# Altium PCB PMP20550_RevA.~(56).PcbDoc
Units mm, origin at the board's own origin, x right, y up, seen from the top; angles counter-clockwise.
Board outline 49.95 x 50.01 mm, 4 copper layers (Top Layer, POWER, GNDS, Bottom Layer), stack 2.028 mm thick; 56 components, 23 nets, 129 pads, 61 vias.
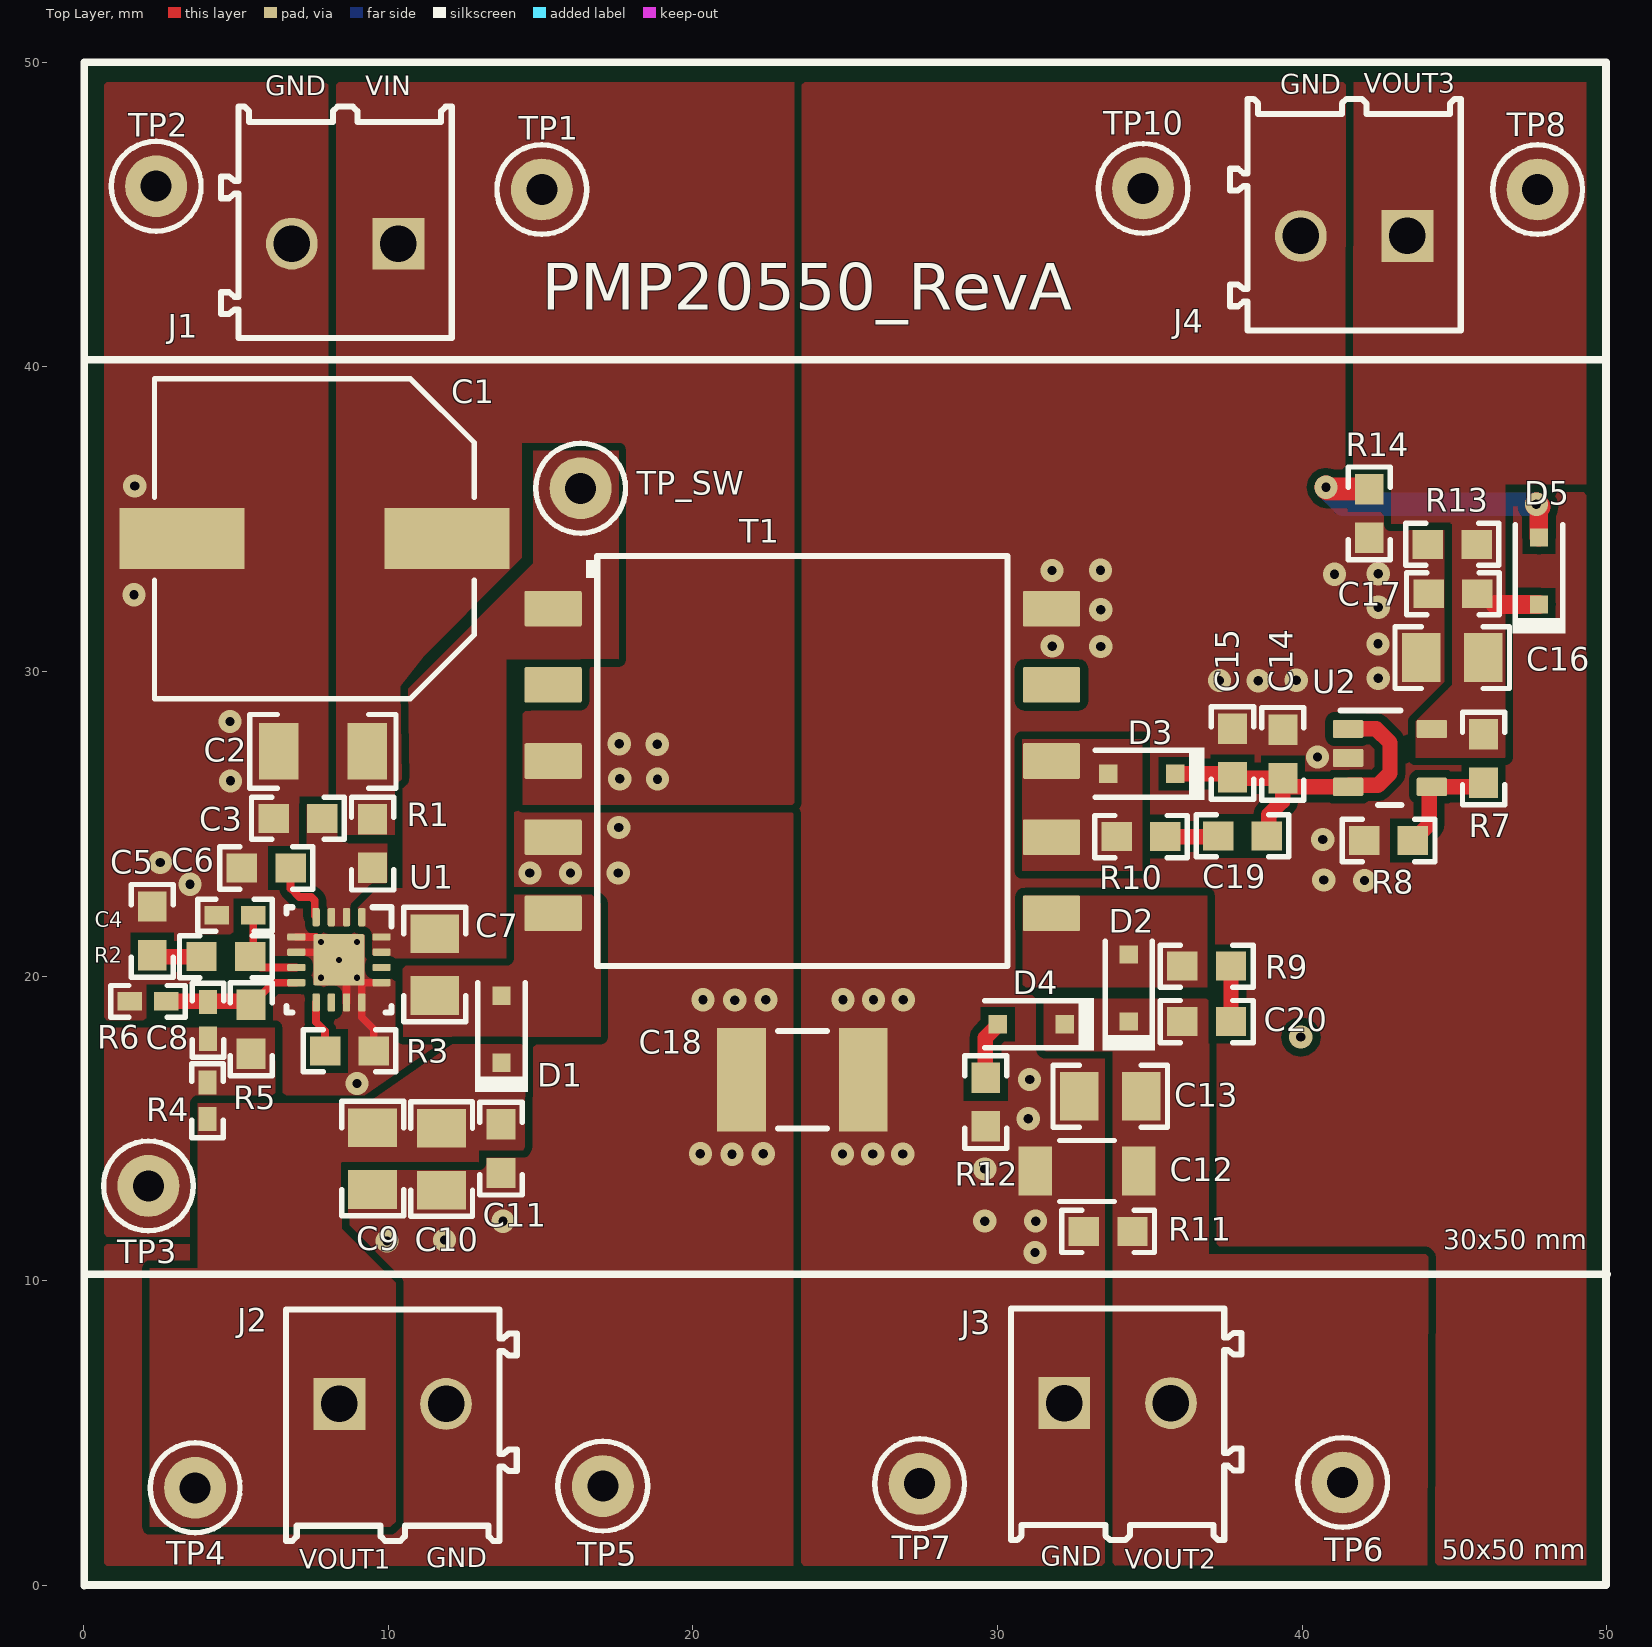
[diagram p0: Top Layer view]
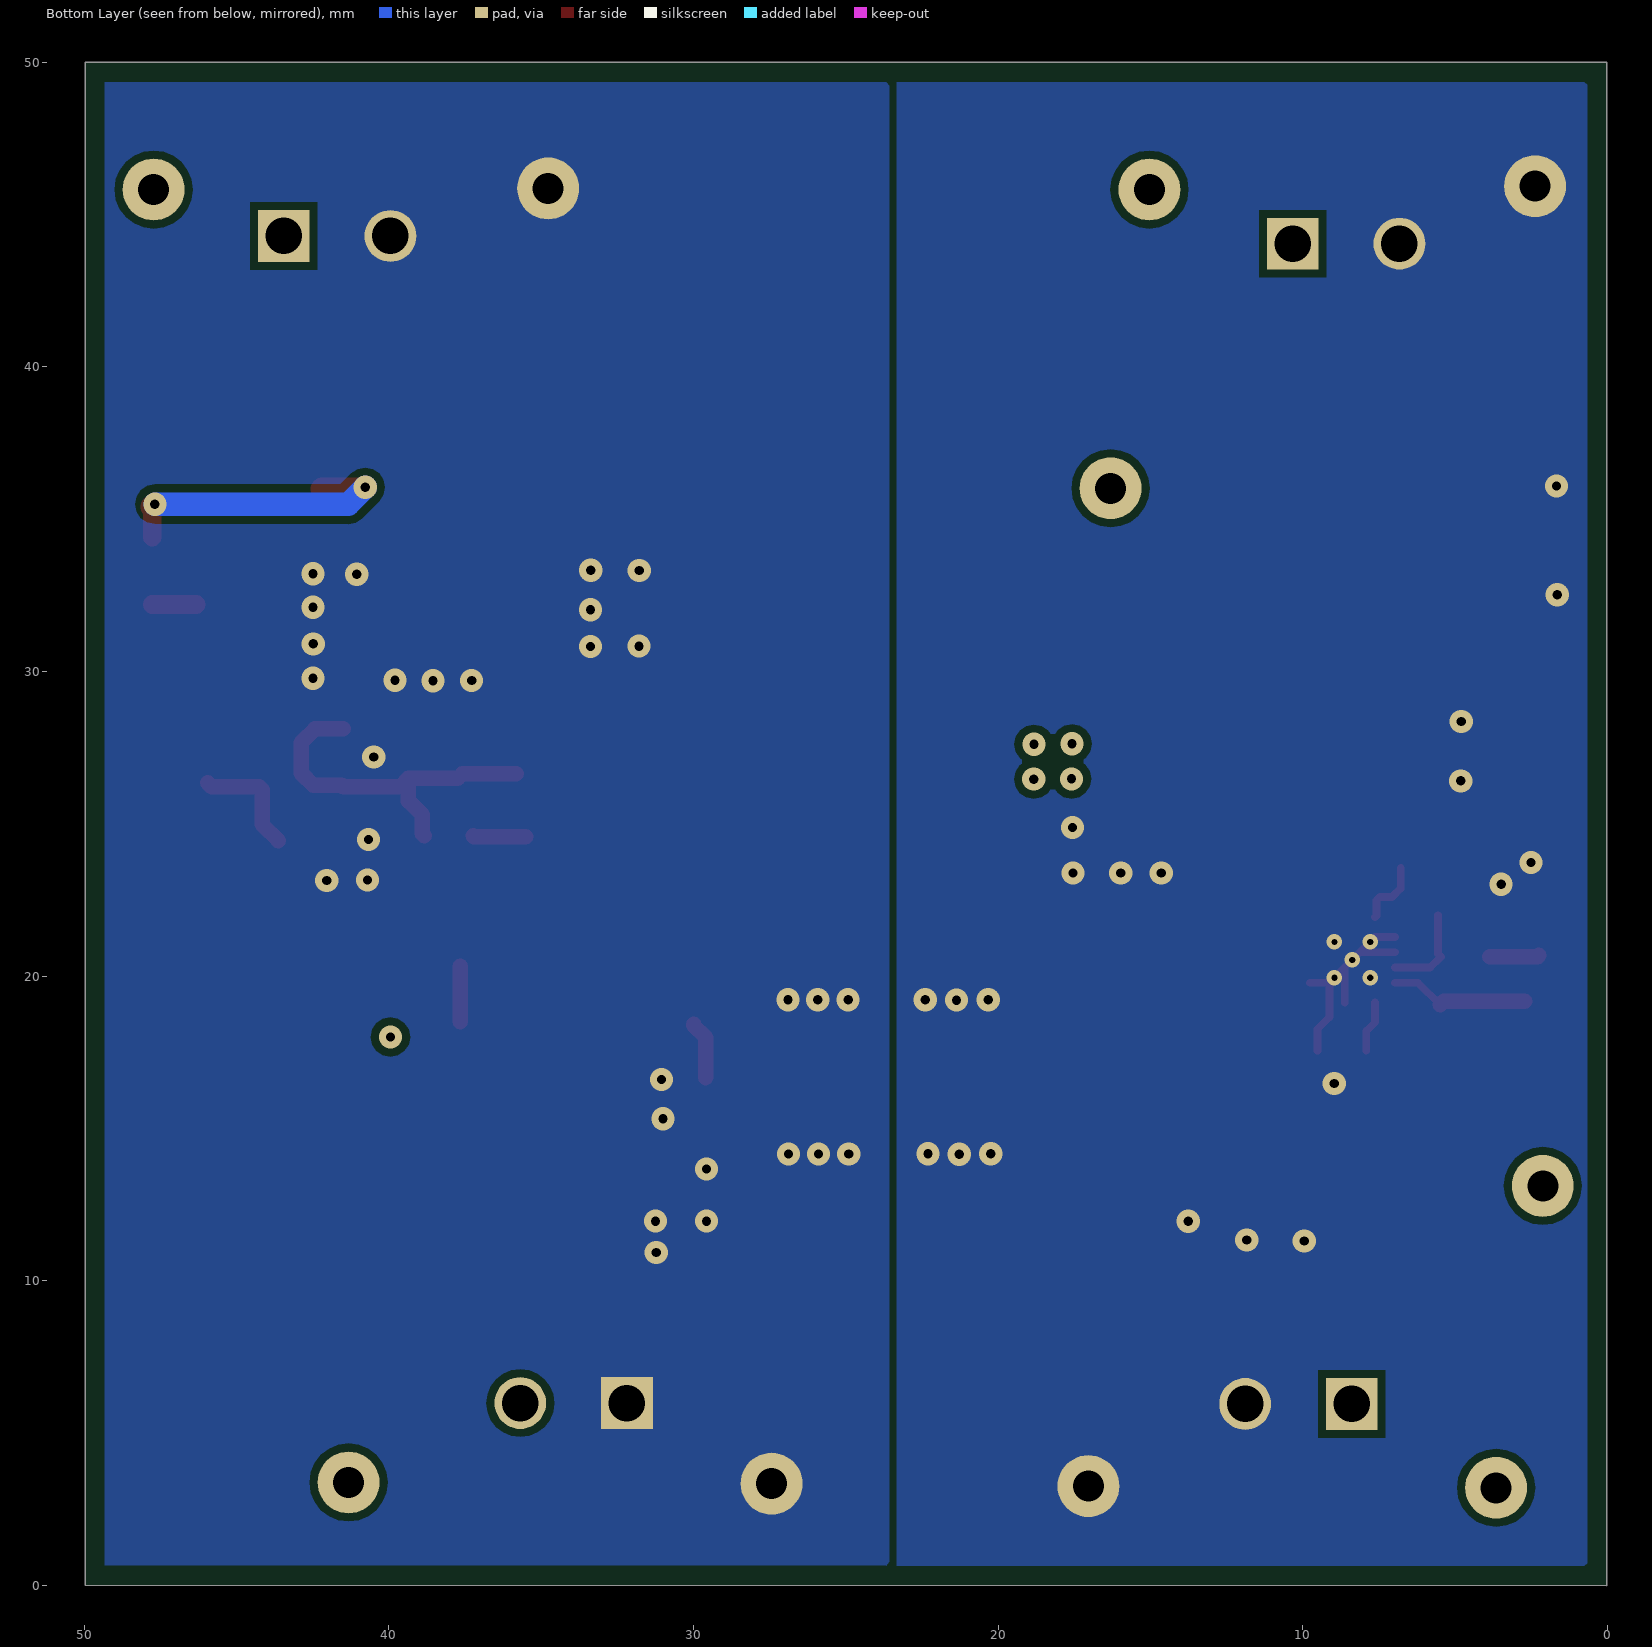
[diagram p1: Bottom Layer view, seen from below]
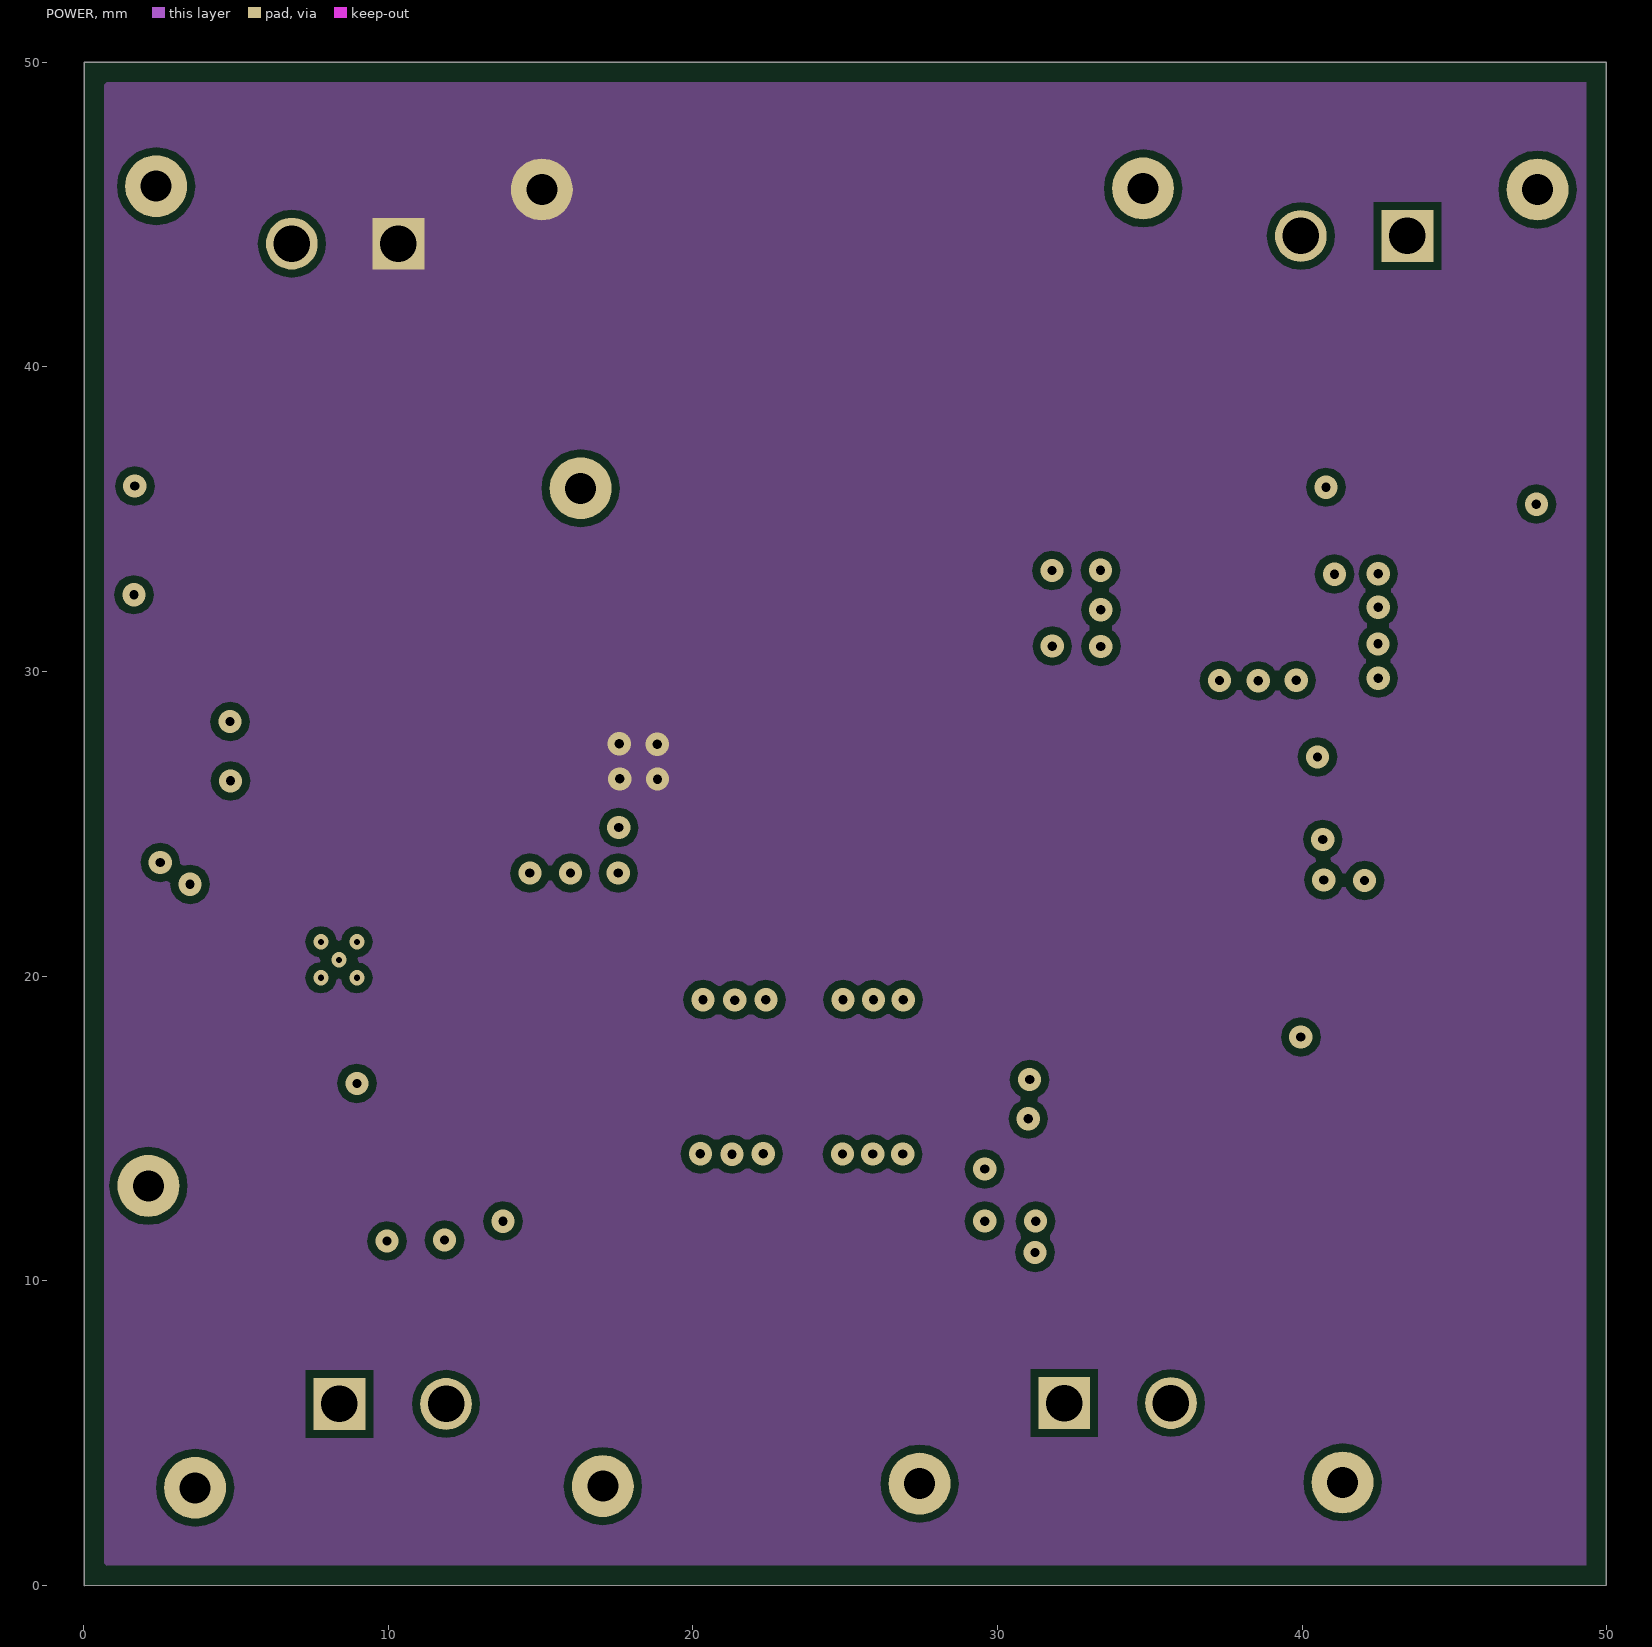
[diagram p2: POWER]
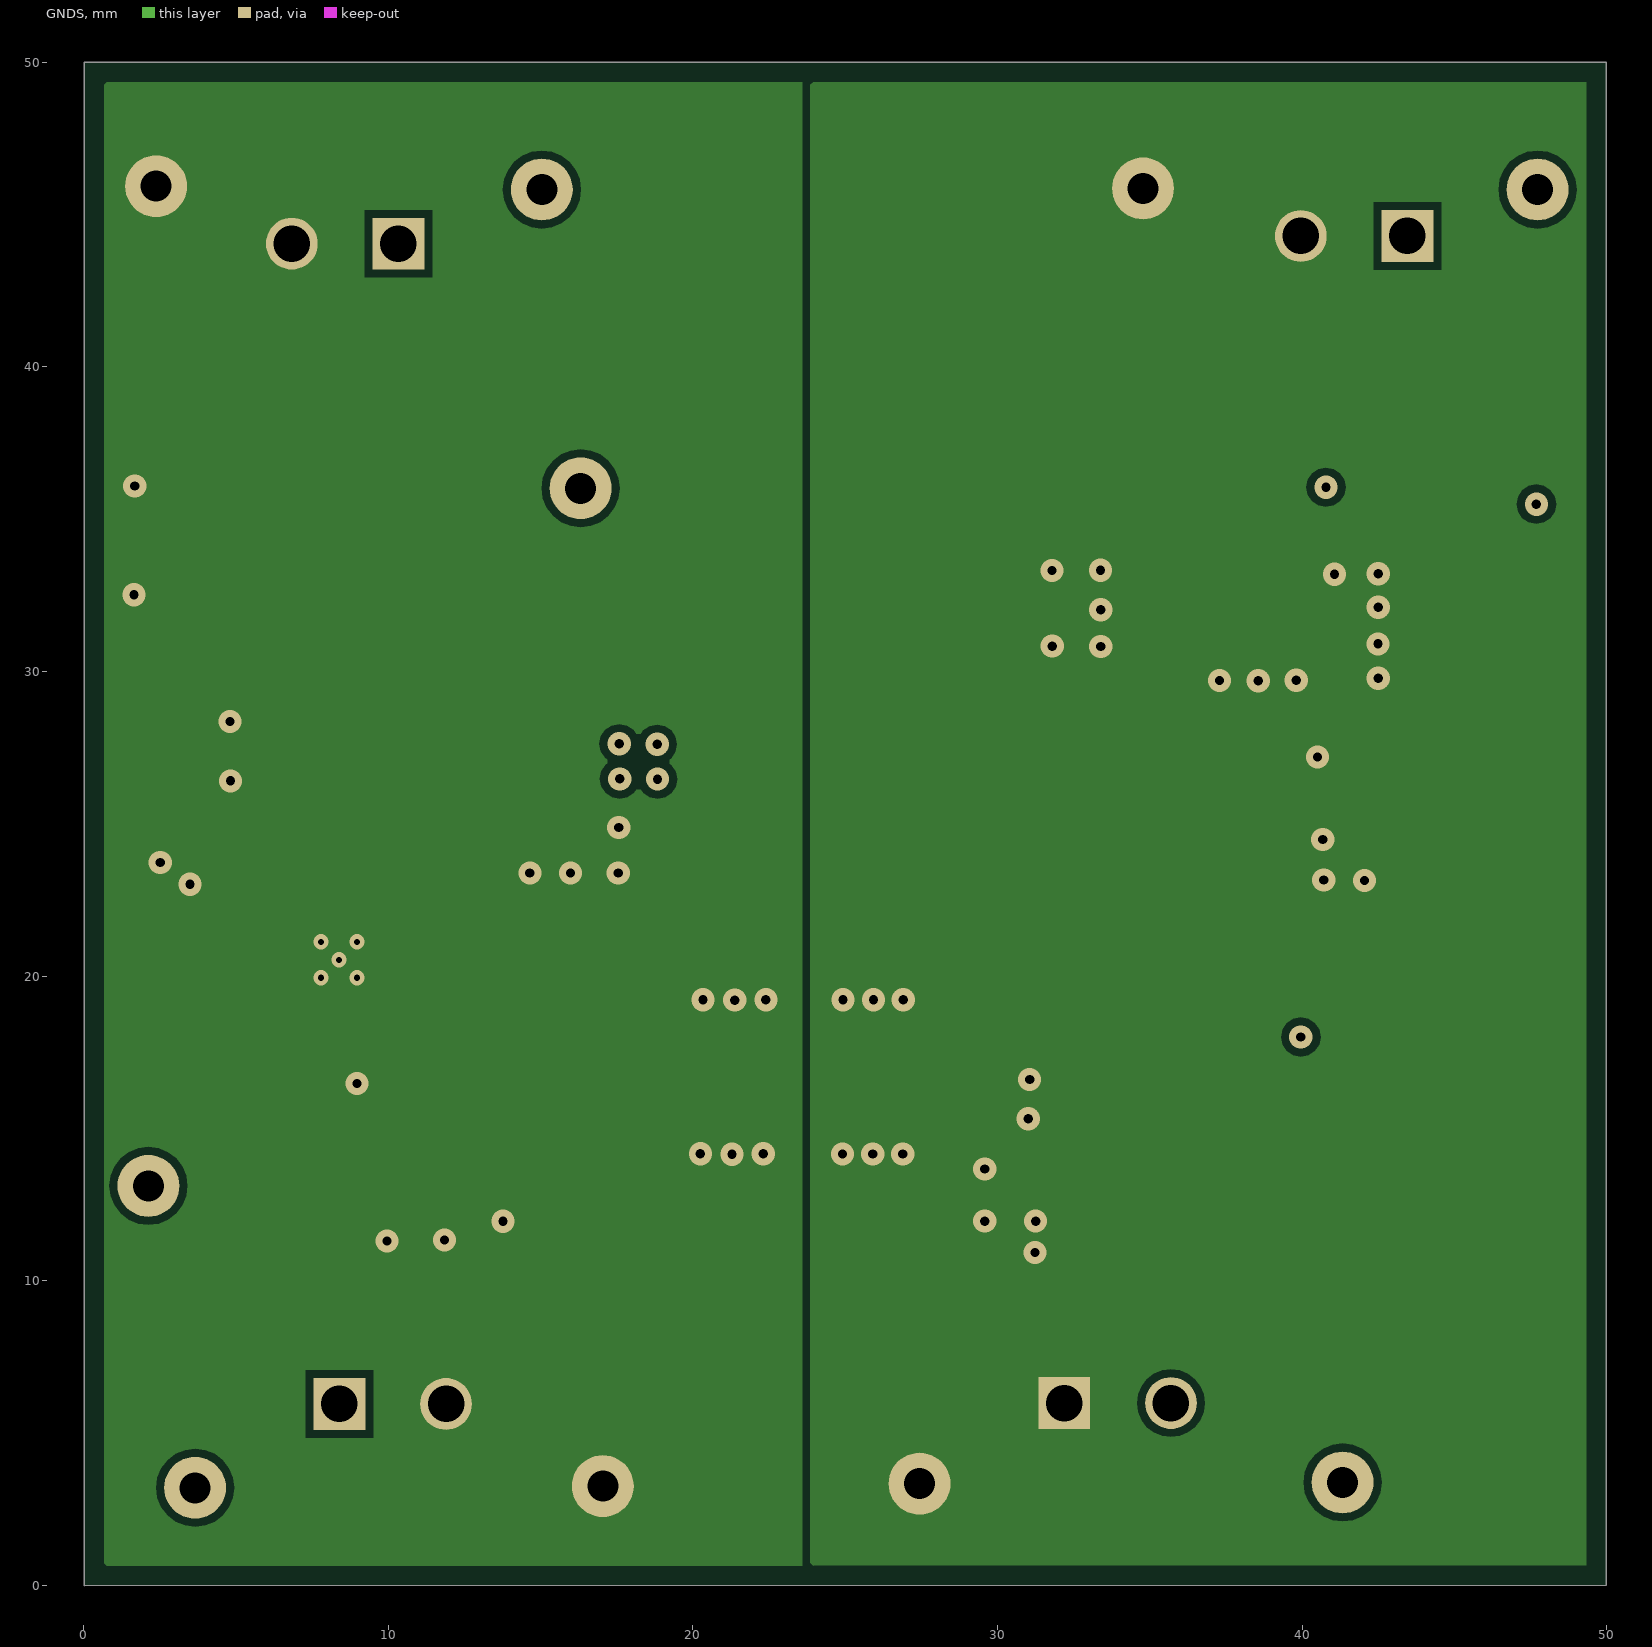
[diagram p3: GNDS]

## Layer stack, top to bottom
Top Solder: solder mask 0.0102, Solder Resist, Dk 3.5
Top Layer: signal copper 0.0356
Dielectric1: core 1.5037, FR-4, Dk 4.8
POWER: signal copper 0.036
Dielectric 3: prepreg 0.127, Dk 4.2
GNDS: signal copper 0.036
Dielectric 2: core 0.254, Dk 4.2
Bottom Layer: signal copper 0.0356
Bottom Solder: solder mask 0.0102, Solder Resist, Dk 3.5

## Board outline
0.019,-0.011 0.019,49.996 0.021,49.994 49.97,49.994 49.972,49.992 49.972,0.008 49.971,0.01

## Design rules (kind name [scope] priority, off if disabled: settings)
AcuteAngle [All] p1: minimum=4.50000000000000E+0001 checktracksonly=FALSE
AssemblyTestPointUsage [All] p1: valid=2
BoardOutlineClearance BoardOutlineClearance_MountingHoles [OnCopper and InComponentClass('Mounting Holes')] p1: gap=1.016
BoardOutlineClearance BoardOutlineClearance_Poly [OnCopper and IsPoly] p2: gap=0.635
BoardOutlineClearance [OnCopper and Not InComponentClass('Logo') and not InComponentClass('FiducialMark') and not InRegion(1000,500,4000,800) and not InPoly] p3: gap=1.016
Clearance Clearance_Keepouts [((IsTrack Or IsArc) And Not InPoly) And IsFree and IsKeepOut vs ((IsTrack Or IsArc) And Not InPoly) And IsFree and IsKeepOut] p1: gap=0
Clearance Clearance_Poly [InPolygon] p2: gap=0.254
Clearance [All] p3: gap=0.127
ComponentClearance ComponentClearance_MountingHoles_FiducialMarks [InComponentClass('Mounting Holes') vs InComponentClass('FiducialMark')] p1: gap=1.27 collisioncheckmode=3 verticalgap=0.254 showdistances=FALSE
ComponentClearance ComponentClearance_Shunt [InComponentClass('Header') vs InComponentClass('Shunt')] p2: gap=0 collisioncheckmode=3 verticalgap=0 showdistances=FALSE
ComponentClearance ComponentClearance_Logo [InComponentClass('Logo')] p3: gap=1.27 collisioncheckmode=3 verticalgap=0.254 showdistances=FALSE
ComponentClearance ComponentClearance_ScrewToNut [(HasFootprint('NY PMS 440 0025 PH')) vs (HasFootprint('Keystone_1902C'))] p4: gap=0.127 collisioncheckmode=3 verticalgap=0.254 showdistances=FALSE
ComponentClearance ComponentClearance_MountingHoles [InComponentClass('Mounting Holes')] p5: gap=6.35 collisioncheckmode=3 verticalgap=2540 showdistances=FALSE
ComponentClearance ComponentClearance_SmallPassives [HasFootprint('0201*') or HasFootprint('0402*') or HasFootprint('0508') or HasFootprint('0603*') or HasFootprint('0612') or HasFootprint('0805*') or HasFootprint('0815*') or HasFootprint('0830*') or HasFootprint('1206*') or HasFootprint('1210*') or HasFootprint('1808*') or HasFootprint('1812*') or HasFootprint('1825*') or HasFootprint('2010*') or HasFootprint('2220*') or HasFootprint('2225*') or HasFootprint('2512*') or HasFootprint('2728*') or HasFootprint('3518*') vs HasFootprint('0201*') or HasFootprint('0402*') or HasFootprint('0508') or HasFootprint('0603*') or HasFootprint('0612') or HasFootprint('0805*') or HasFootprint('0815*') or HasFootprint('0830*') or HasFootprint('1206*') or HasFootprint('1210*') or HasFootprint('1808*') or HasFootprint('1812*') or HasFootprint('1825*') or HasFootprint('2010*') or HasFootprint('2220*') or HasFootprint('2225*') or HasFootprint('2512*') or HasFootprint('2728*') or HasFootprint('3518*')] p6: gap=0.38 collisioncheckmode=3 verticalgap=0.254 showdistances=FALSE
ComponentClearance ComponentClearance_THtoSMT [IsThruComponent vs IsSMTComponent] p7: gap=1.016 collisioncheckmode=3 verticalgap=0.762 showdistances=FALSE
ComponentClearance ComponentClearance_THtoTH [IsThruComponent vs IsThruComponent] p8: gap=0.762 collisioncheckmode=3 verticalgap=0.762 showdistances=FALSE
ComponentClearance [All] p9: gap=0.762 collisioncheckmode=3 verticalgap=0.254 showdistances=FALSE
DiffPairsRouting [All] p1: maxlimit=2.54 minlimit=0.254 mostfreqgap=0.254 toplayer_minwidth=0.381 toplayer_maxwidth=0.381 toplayer_prefwidth=0.381 midlayer1_minwidth=0.381 midlayer1_maxwidth=0.381 midlayer1_prefwidth=0.381 midlayer2_minwidth=0.381 midlayer2_maxwidth=0.381 midlayer2_prefwidth=0.381 bottomlayer_minwidth=0.381 bottomlayer_maxwidth=0.381 bottomlayer_prefwidth=0.381 maxuncoupledlength=25.4
FabricationTestPointUsage TestPointUsage [All] p1: valid=2 allowmultiple=FALSE
FabricationTestpoint Testpoint [All] p1: side=3 testpointundercomponent=TRUE minsize=1.016 maxsize=2.54 preferedsize=1.524 minholesize=0 maxholesize=1.016 preferedholesize=0.813 testpointgrid=0.025 allowsidetop=TRUE allowsidebottom=TRUE usegrid=TRUE gridtolerance=0
FanoutControl Fanout_LCC [IsLCC] p1: bgadir=Out bgaviamode=Centered fanoutstyle=Auto fanoutdirection=Alternating viagrid=0.025 // Fanout_LCC (Default Rule)
FanoutControl Fanout_BGA [IsBGA] p2: bgadir=Out bgaviamode=Centered fanoutstyle=Auto fanoutdirection=Alternating viagrid=0.025 // Fanout_BGA (Default Rule)
FanoutControl Fanout_Default [All] p4: bgadir=Out bgaviamode=Centered fanoutstyle=Auto fanoutdirection=Alternating viagrid=0.025 // Fanout_Default (Default Rule)
FanoutControl Fanout_Small [(CompPinCount < 5)] p5: bgadir=Out bgaviamode=Centered fanoutstyle=Auto fanoutdirection=OutThenIn viagrid=0.025 // Fanout_Small (Default Rule)
HoleSize [All] p1: absolutevalues=TRUE maxlimit=6.375 minlimit=0.2 maxpercent=80.000 minpercent=20.000
MinimumAnnularRing MinimumAnnularRing_ThermalPadVias [IsVia and InAnyComponent] p1: minimumring=0.15
MinimumAnnularRing [All] p2: minimumring=0.203
MinimumSolderMaskSliver MinimumSolderMaskSliver_Logo [InComponentClass('Logo') vs InComponentClass('Logo')] p1: minsoldermaskwidth=0.018
MinimumSolderMaskSliver [All] p2: minsoldermaskwidth=0.1
PlaneConnect [All] p1: planeconnectstyle=Direct reliefexpansion=0.254 reliefentries=4 reliefconductorwidth=0.254 reliefairgap=0.254
PolygonConnect [All] p1: connectstyle=Direct reliefconductorwidth=0.254 reliefentries=4 polygonreliefangle="90 Angle" airgapwidth=0.254
RoutingVias ThermalPadVias [IsVia and InAnyComponent] p1: holewidth=0.2 width=0.5 viastyle="Through Hole" minholewidth=0.2 minwidth=0.5 maxholewidth=0.33 maxwidth=0.6
RoutingVias [All] p2: holewidth=0.406 width=0.864 viastyle="Through Hole" minholewidth=0.2 minwidth=0.66 maxholewidth=1.016 maxwidth=1.651
SilkToBoardRegionClearance [Not ((IsComment or IsDesignator) And (Hide <> 'False')) and not InRegion(1000,500,4000,800)] p1:
SilkToSilkClearance SilkToSilkClearance_Pb-FreeLogo [(HasFootprint('Pb-Free_Overlay_Medium') OR HasFootprint('Pb-Free_Overlay_Small')) vs (HasFootprint('Pb-Free_Overlay_Medium') OR HasFootprint('Pb-Free_Overlay_Small'))] p1: silktosilkclearance=0
SilkToSilkClearance [All] p2: silktosilkclearance=0
SilkToSolderMaskClearance SilkToComponentPadClearance [IsPad and InAnycomponent] p1: minsilkscreentomaskgap=0.127 clearancetoexposedcopper=TRUE
SilkToSolderMaskClearance "Silk to Solder Mask Opening" [All] p2: minsilkscreentomaskgap=0.102 clearancetoexposedcopper=FALSE
SolderMaskExpansion [All] p1: expansion=0.05
Width [All] p1: maxlimit=2.54 minlimit=0.152 preferedwidth=0.254 checkconnectedcopper=TRUE
15 further rules are at their usual default settings.

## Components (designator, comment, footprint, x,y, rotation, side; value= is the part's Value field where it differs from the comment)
C1 "EEE-FC1V221P" SM_RADIAL_G 7.574,34.358 r180 top
C2 "GMK316AB7106KL" 1206 7.85,27.378 r180 top
C3 "C1608X7R1E104K080AA" 0603 7.031,25.179 r180 top
C4 "GRM155R71E333KA88D" 0402 4.962,21.998 r180 top
C5 "C1608X7R1E104K080AA" 0603 2.249,21.484 r90 top
C6 "C1608X7R1E104K080AA" 0603 5.991,23.549 r180 top
C7 "LMK212B7105KG-T" 0805_HV 11.52,20.379 r90 top
C8 "GRM1555C1H201JA01D" 0402 4.079,18.549 r90 top
C9 "GRM21BZ71A226ME15L" 0805_HV 9.483,14.008 r270 top
C10 "GRM21BZ71A226ME15L" 0805_HV 11.745,13.991 r270 top
C11 "C0603X104K8RACTU" 0603 13.696,14.336 r270 top
C12 "C3216X5R1E336M160AC" 1206_180 32.928,13.604 r180 top
C13 "08053C104KAT2A" 0805_HV 33.698,16.058 r180 top
C14 "GRM188Z71A106MA73D" 0603 39.362,27.294 r90 top
C15 "C1608X7R1E104K080AA" 0603 37.711,27.322 r90 top
C16 "C2012X7R1E474K125AA" 0805_HV 44.924,30.457 r180 top
C17 "C0603X104K8RACTU" 0603 44.947,32.552 r180 top
C18 "GR443QR73D102KW01L" 1812 23.59,16.598 r180 top
C19 "GRM1885C1H111JA01D" 0603 38.039,24.604 r180 top
C20 "GRM1885C1H111JA01D" 0603 36.861,18.506 r0 top
D1 "PMEG2020EJ,115" SOD-323F 13.713,18.255 r90 top
D2 "PMEG2020EJ,115" SOD-323F 34.302,19.612 r90 top
D3 "PMEG2020EJ,115" SOD-323F 34.728,26.641 r180 top
D4 "MMSZ5235BS-7-F" SOD-323 31.101,18.418 r180 top
D5 "MMSZ5235BS-7-F" SOD-323 47.77,33.299 r90 top
J1 "1984617" Phoenix_1984617 8.58,44.042 r180 top
J2 "1984617" Phoenix_1984617 10.143,5.956 r0 top
J3 "1984617" Phoenix_1984617 33.94,5.983 r0 top
J4 "1984617" Phoenix_1984617 41.703,44.297 r180 top
R1 "ERJ-3GEY0R00V" 0603 9.483,24.35 r90 top
R2 "RC0603FR-073K01L" 0603 4.666,20.638 r0 top
R3 "CRCW0603162KFKEA" 0603 8.723,17.547 r180 top
R4 "ERJ-2RKF49R9X" 0402 4.062,15.907 r270 top
R5 "CRCW060330K9FKEA" 0603 5.495,18.255 r270 top
R6 "ERJ-2RKF1002X" 0402 2.111,19.17 r0 top
R7 "RC0603FR-0778K7L" 0603 45.953,27.143 r90 top
R8 "CRCW060324K9FKEA" 0603 42.833,24.45 r0 top
R9 "CPF0603B1K62E" 0603 36.861,20.324 r180 top
R10 "CPF0603B1K62E" 0603 34.705,24.581 r180 top
R11 "CPF0603B1K62E" 0603 33.627,11.618 r180 top
R12 "CPF0603B1K62E" 0603 29.609,15.864 r270 top
R13 "CPF0603B1K62E" 0603 44.924,34.173 r180 top
R14 "CPF0603B1K62E" 0603 42.198,35.187 r270 top
T1 "750316553" Wurth_750316553 23.588,27.06 r0 top
TP1 "5000" Keystone5000 15.038,45.82 r90 top
TP2 "5001" Keystone5001 2.377,45.929 r90 top
TP3 "5003" Keystone5003 2.124,13.113 r0 top
TP4 "VBUS" Keystone5000 3.656,3.203 r90 top
TP5 "5001" Keystone5001 17.039,3.257 r90 top
TP6 "5000" Keystone5000 41.326,3.378 r0 top
TP7 "5001" Keystone5001 27.438,3.338 r0 top
TP8 "5000" Keystone5000 47.725,45.82 r0 top
TP10 "5001" Keystone5001 34.774,45.857 r90 top
TP_SW "5001" Keystone5001 16.312,36.013 r90 top
U1 "TPS55340QRTERQ1" RTE0016C 8.378,20.534 r270 top
U2 "TPS73201QDBVRQ1" DBV0005A_N 42.88,27.162 r0 top

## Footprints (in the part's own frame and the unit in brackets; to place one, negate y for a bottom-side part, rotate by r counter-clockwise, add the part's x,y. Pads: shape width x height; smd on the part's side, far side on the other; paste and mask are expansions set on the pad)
0402 [mm] "0402 from SM-752 data"
  rect 0.8x0.6 smd: 1(-0.6,0) 2(0.6,0)
  silkscreen extent -1.22,-0.52 1.22,0.52, body extent -0.55,-0.3 0.55,0.3, height 0.6
0603 [mm] "0603 from SM-752 data"
  rect 1x0.95 smd: 1(-0.8,0) 2(0.8,0)
  silkscreen extent -1.52,-0.69 1.52,0.69, body extent -0.87,-0.47 0.87,0.47, height 1
0805_HV [mil] "0805 with 30mil clearance between pads"
  rect 50x63 smd: 1(-40,0) 2(40,0)
  silkscreen extent -74,-40 74,40, body extent -43,-29 43,29, height 57
1206 [mm] "1206 from SM-752 data"
  rect 1.3x1.85 smd: 1(-1.45,0) 2(1.45,0)
  silkscreen extent -2.4,-1.21 2.4,1.21, body extent -1.7,-0.9 1.7,0.9, height 1.35
1206_180 [mm] "1206_180"
  rect 1.1x1.6 smd: 1(-1.7,0) 2(1.7,0)
  silkscreen extent -0.9,-1 0.9,1, body extent -1.75,-0.95 1.75,0.95, height 1.8
1812 [mm]
  rect 1.6x3.4 smd: 1(-2,0) 2(2,0)
  silkscreen extent -0.8,-1.6 0.8,1.6, body extent -2.4,-1.7 2.4,1.7, height 1.35
DBV0005A_N [mm] "SOT23, 5-Leads, Body 2.9x1.6mm, Pitch 0.95mm, Lead Span 2.8mm, IPC Medium Density"
  rrect17% 1x0.6 smd: 1(-1.375,0.95) 2(-1.375,0) 3(-1.375,-0.95) 4(1.375,-0.95) 5(1.375,0.95)
  silkscreen extent -1.63,-1.55 0.38,1.55, body extent -1.42,-1.46 1.42,1.46, height 1.09
Keystone5000 [mil] "For Keystone 500x miniature loop terminals"
  round 80 hole 40: 1(0,0)
  silkscreen extent -58,-58 58,58, body extent -49,-49 49,49, height 182
Keystone5001 [mil] "For Keystone 500x miniature loop terminals"
  round 80 hole 40: 1(0,0)
  silkscreen extent -58,-58 58,58, body extent -49,-49 49,49, height 182
Keystone5003 [mil] "For Keystone 500x miniature loop terminals"
  round 80 hole 40: 1(0,0)
  silkscreen extent -58,-58 58,58, body extent -49,-49 49,49, height 182
Phoenix_1984617 [mm] "Terminal Block, 3.5mm, 2x1, TH"
  rect 1.7x1.7 hole 1.2: 1(-1.75,0)
  round 1.7 hole 1.2: 2(1.75,0)
  silkscreen extent -3.5,-4.5 4.07,3.1, body extent -3.5,-4.5 4.07,3.1, height 9
RTE0016C [mm] "Texas Insturments"
  rrect42% 0.6x0.24 smd: 1(-1.4,0.75) 2(-1.4,0.25) 3(-1.4,-0.25) 4(-1.4,-0.75) 9(1.4,-0.75) 10(1.4,-0.25) 11(1.4,0.25) 12(1.4,0.75)
  rrect42% 0.24x0.6 smd: 5(-0.75,-1.4) 6(-0.25,-1.4) 7(0.25,-1.4) 8(0.75,-1.4) 13(0.75,1.4) 14(0.25,1.4) 15(-0.25,1.4) 16(-0.75,1.4)
  rrect6% 1.55x1.55 on Top Paste: 17(0,0)
  rrect6% 1.68x1.68 smd paste-0.85: 17(0,0)
  silkscreen extent -1.72,-1.73 1.72,1.73, body extent -1.57,-1.57 1.58,1.58, height 0.81
SM_RADIAL_G [mm] "10 x 10.2mm:  Panasonic G"
  rect 4.1x2 smd: 1(-4.35,0) 2(4.35,0)
  silkscreen extent -5.25,-5.25 5.25,5.25, body extent -5.25,-5.25 5.25,5.25, height 10.5
SOD-323 [mm] "NXP recommended land pattern"
  rect 0.6x0.6 smd paste-0.05: 1(-1.1,0) 2(1.1,0)
  silkscreen extent -2.06,-0.86 1.53,0.86, body extent -1.3,-0.67 1.3,0.68, height 1.1
SOD-323F [mm] "NXP recommended land pattern"
  rect 0.6x0.6 smd paste-0.05: 1(-1.1,0) 2(1.1,0)
  silkscreen extent -2.06,-0.86 1.53,0.86, body extent -1.35,-0.67 1.35,0.68, height 0.79
Wurth_750316553 [mm] "SMD, 10-Leads, Body 17.75x13.46mm, Pitch 2.5mm"
  rrect9% 1.88x1.17 smd: 1(-8.18,5) 2(-8.18,2.5) 3(-8.18,0) 4(-8.18,-2.5) 5(-8.18,-5) 6(8.18,-5) 7(8.18,-2.5) 8(8.18,0) 9(8.18,2.5) 10(8.18,5)
  silkscreen extent -7.1,-6.73 6.73,6.73, body extent -8.87,-6.73 8.88,6.73, height 12.7

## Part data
C1: "CAP, AL, 220 µF, 35 V, +/- 20%, 0.15 ohm, SMD"
C2: "CAP, CERM, 10 µF, 35 V, +/- 10%, X7R, 1206"
C3 C5 C6 C15: "CAP, CERM, 0.1 µF, 25 V, +/- 10%, X7R, 0603"
C4: "OPEN, 0402"
C7: "CAP, CERM, 1 µF, 10 V, +/- 10%, X7R, 0805"
C8: "CAP, CERM, 200 pF, 50 V, +/- 5%, C0G/NP0, 0402"
C9 C10: "CAP, CERM, 22 µF, 10 V, +/- 20%, X7R, 0805"
C11 C17: "CAP, CERM, 0.1 µF, 10 V, +/- 10%, X7R, 0603"
C12: "CAP, CERM, 33 µF, 25 V, +/- 20%, X5R, 1206"
C13: "CAP, CERM, 0.1 µF, 25 V, +/- 10%, X7R, 0805"
C14: "CAP, CERM, 10 µF, 10 V, +/- 20%, X7R, 0603"
C16: "CAP, CERM, 4.7 µF, 25 V, +/- 10%, X7R, 0805"
C18: "CAP, CERM, 1000 pF, 2000 V, +/- 10%, X7R, 1812"
C19 C20: "CAP, CERM, 110 pF, 50 V, +/- 5%, C0G/NP0, 0603"
D1 D2 D3: "Diode, Schottky, 20 V, 2 A, SOD-323F"
D4 D5: "Diode, Zener, 6.8 V, 200 mW, SOD-323"
J1 J2 J3 J4: "Terminal Block, 3.5mm, 2x1, TH"
R1: "RES, 0, 5%, 0.1 W, 0603"
R2: "RES, 3.01 k, 1%, 0.1 W, 0603"
R3: "RES, 162 k, 1%, 0.1 W, 0603"
R4: "RES, 49.9, 1%, 0.1 W, AEC-Q200 Grade 0, 0402"
R5: "RES, 30.9 k, 1%, 0.1 W, 0603"
R6: "RES, 10.0 k, 1%, 0.1 W, 0402"
R7: "RES, 78.7 k, 1%, 0.1 W, 0603"
R8: "RES, 24.9 k, 1%, 0.1 W, 0603"
R9 R10 R11 R12 R13 R14: "RES, 1.62 k, 0.1%, 0.063 W, 0603"
T1: "Transformer, 52 uH, SMT"
TP1 TP6 TP8: "Test Point, Miniature, Red, TH"
TP2 TP5 TP7 TP10 TP_SW: "Test Point, Miniature, Black, TH"
TP3: "Test Point, Miniature, Orange, TH"
TP4: library part 5000, "Test Point, TH, Miniature, Red"
U1: "Integrated 5-A 40-V Wide Input Range Boost/SEPIC/Flyback DC-DC Regulator, RTE0016C"
U2: "Single Output Fast Transient Response LDO, 250 mA, Adjustable 1.2 to 5.5 V Output, 1.7 to 5.5 V Input, 5-pin SOT-23 (DBV), -40 to 125 degC, Green (RoHS & no Sb/Br)"

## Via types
v1: diameter 0.762, hole 0.305, Top Layer to Bottom Layer, 32 vias
v2: diameter 0.762, hole 0.305, Top Layer to Bottom Layer, tented top, 22 vias
v3: diameter 0.5, hole 0.2, Top Layer to Bottom Layer, tented top, 5 vias
v4: diameter 0.762, hole 0.305, Top Layer to Bottom Layer, tented both sides, 2 vias

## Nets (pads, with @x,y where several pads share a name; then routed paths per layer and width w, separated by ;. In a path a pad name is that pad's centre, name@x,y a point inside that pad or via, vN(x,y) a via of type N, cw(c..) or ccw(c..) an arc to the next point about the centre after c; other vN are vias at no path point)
GND: C1.2 C2.2 C3.2 C4.2 C5.2 C6.2 C9.2 C10.2 C11.2 C18.2 J1.2 J2.2 R3.1 R6.1 T1.4 TP2.1 TP5.1 U1.5 U1.6 U1.11 U1.12 U1.13 U1.17@8.378,20.534 | length 7.9
  Top Layer w0.254: U1.6 U1.17@8.128,20.784 ; U1.5 U1.17@7.628,21.284 ; v3(7.788,21.124) U1.17@8.128,20.784 ; U1.11 U1.17@8.628,20.284 ; R3.1 9.523,18.252 9.128,18.648 U1.12 U1.17@9.128,19.784 ; U1.13 U1.17@9.128,19.784 ; U1.17@8.128,20.784 v3(8.378,20.534) U1.17@8.628,20.284 ; U1.17@8.628,20.284 U1.17@9.128,19.784
  other v1: 21.281,14.151 20.242,14.166 22.306,14.166 21.369,19.211 20.33,19.225 22.393,19.225 14.645,23.38 15.976,23.382 17.547,23.382 17.563,24.874 1.647,32.518 1.677,36.085
  other v2: 9.954,11.303 11.841,11.336 13.762,11.954 8.967,16.477 3.491,23.012 2.511,23.73 4.817,26.408 4.803,28.355
  other v3: 7.788,19.944 8.968,19.944 8.968,21.124
GND2: C12.2 C13.2 C14.2 C15.2 C16.2 C17.2 C18.1 J3.1 J4.2 R8.1 R11.2 R12.2 R13.2 R14.2 T1.10 TP7.1 TP10.1 U2.2
  other v1: 31.23,10.927 29.576,11.956 31.248,11.956 24.907,14.157 25.902,14.157 26.883,14.157 31.005,15.314 31.051,16.604 24.927,19.225 25.922,19.225 26.903,19.225 33.386,30.822 31.793,30.831 33.386,32.024 31.784,33.314 33.378,33.322
  other v2: 29.576,13.665 42.044,23.139 40.707,23.157 40.673,24.486 40.502,27.194 37.287,29.702 38.556,29.693 39.802,29.712 42.494,29.779 42.487,30.906 42.494,32.11 41.056,33.194 42.494,33.208
NetC1_1: C1.1 C2.1 J1.1 R1.2 T1.3 TP1.1
  other v1: 17.594,26.474 18.835,26.466 18.827,27.608 17.578,27.624
NetC3_1: C3.1 R1.1 U1.2 U1.3
NetC4_1: C4.1 R2.2 U1.7 | length 3.1
  Top Layer w0.254: C4.1 5.562,20.734 R2.2 5.819,20.284 U1.7
NetC5_1: C5.1 R2.1 | length 1.6
  Top Layer w0.508: C5.1 2.295,20.638 R2.1
NetC6_1: C6.1 U1.4 | length 2.2
  Top Layer w0.254: C6.1 6.791,22.879 7.075,22.595 7.47,22.595 7.586,22.479 7.586,21.976 U1.4
NetC7_1: C7.1 D1.2 T1.5
NetC7_2: C7.2 T1.1 TP_SW.1 U1.1 U1.15 U1.16
NetC8_1: C8.1 R4.1 R5.2 TP3.1
NetC8_2: C8.2 R5.1 R6.2 U1.8 | length 4.6
  Top Layer w0.254: R5.1 6.224,19.784 U1.8
  Top Layer w0.508: R6.2 5.38,19.17 R5.1
NetC9_1: C9.1 C10.1 C11.1 D1.1 J2.1 R4.2 TP4.1
NetC12_1: C12.1 C13.1 C20.1 D2.1 D4.1 J3.2 R11.1 TP6.1
NetC14_1: C14.1 C15.1 C19.1 D3.1 U2.1 U2.3 | length 12.1
  Top Layer w0.508: D3.1 37.593,26.641 C15.1 37.739,26.494 C14.1 ; C19.1 38.903,24.667 38.903,25.295 39.352,25.744 39.362,25.744 C14.1 ; U2.1 42.43,28.112 42.88,27.662 42.88,26.658 42.479,26.258 41.55,26.258 U2.3 39.643,26.212 C14.1
NetC16_1: C16.1 C17.1 D5.1 J4.1 R7.2 R13.1 TP8.1 U2.5 | length 1.5
  Top Layer w0.508: 46.294,32.232 46.327,32.199
  Top Layer w0.61: 46.327,32.199 D5.1
NetC19_2: C19.2 R10.1 | length 1.7
  Top Layer w0.508: R10.1 37.217,24.581 C19.2
NetC20_2: C20.2 R9.1 | length 1.8
  Top Layer w0.508: C20.2 R9.1
NetD2_2: D2.2 R9.2 T1.6
NetD3_2: D3.2 R10.2 T1.7 T1.8
NetD4_2: D4.2 R12.1 | length 1.9
  Top Layer w0.508: R12.1 29.597,16.676 29.597,17.978 30.001,18.382 D4.2
NetD5_2: D5.2 R14.1 | length 9.7
  Top Layer w0.61: D5.2 v4@47.77,35.405
  Top Layer w0.762: v4(40.779,36.047) 40.838,35.987 R14.1 ; v4(47.685,35.49) v4@47.77,35.405
  Bottom Layer w0.762: v4(40.779,36.047) 41.34,35.486 41.344,35.49 v4(47.685,35.49)
NetR3_2: R3.2 U1.9 | length 1.7
  Top Layer w0.254: U1.9 7.628,18.49 7.923,18.194 R3.2
NetR7_1: R7.1 R8.2 U2.4 | length 3.8
  Top Layer w0.508: R8.2 44.162,24.979 44.162,26.119 U2.4 45.823,26.212 R7.1
pads on no net: T1.2 T1.9 U1.10 U1.14 U1.17@8.378,20.534
copper on no net:
  other v2: 39.952,18

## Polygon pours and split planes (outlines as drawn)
GND2 on Top Layer "top - gnd2" (solid, pour order 32): 23.35,49.969 23.374,49.992 49.972,49.992 49.972,0.008 49.964,0 23.231,0
GND on Top Layer "top-gnd1" (solid, pour order 30): 0.019,49.996 23.204,49.996 23.231,49.969 23.29,49.909 23.29,0.298 0.328,0.298 0.019,-0.011
NetC3_1 on Top Layer "Top Layer-No Net 4" (solid, pour order 28): 7.341,25.639 7.323,25.621 7.323,22.99 7.985,22.355 7.985,21.599 8.463,21.599 8.771,21.599 8.771,21.914 9.941,23.083 9.957,23.1 9.957,24.35 8.685,24.35 8.581,24.454 8.314,24.721 8.314,25.647
NetC8_1 on Top Layer "Top Layer-No Net 3" (solid, pour order 26): 6.27,18.297 0.431,18.297 0.522,18.207 0.522,11.449 3.72,11.449 3.733,11.436 3.742,11.445 3.742,15.828 6.28,15.828
NetD3_2 on Top Layer "Top Layer-No Net 2" (solid, pour order 24): 30.809,27.781 34.75,27.781 34.75,23.45 30.809,23.45
NetD2_2 on Top Layer "Top Layer-No Net 1" (solid, pour order 22): 30.833,22.654 30.833,19.873 30.833,19.631 31.044,19.631 36.887,19.631 36.887,22.639
NetC7_1 on Top Layer "Top Layer-No Net" (solid, pour order 14): 10.472,20.842 12.302,22.672 14.469,22.672 16.677,22.672 16.858,22.49 16.966,22.383 16.966,18.011 10.49,18.011
NetC16_1 on Top Layer "VOUT3" (solid, pour order 12): 41.689,49.811 49.753,49.811 49.753,37.941 49.753,36.137 46.667,36.137 46.667,33.592 46.667,27.154 46.678,27.143 46.645,27.175 43.722,27.175 43.722,28.36 44.856,29.494 44.924,29.562 44.924,34.648 44.924,34.854 41.689,34.854 41.667,38.592
NetC12_1 on Top Layer "VOUT2" (solid, pour order 10): 44.103,0.129 33.823,0.129 33.762,0.068 33.774,0.08 33.774,17.539 31.573,17.539 31.508,17.604 31.508,19.264 36.847,19.264 36.857,19.253 36.941,19.169 36.941,17.688 36.941,16.326 36.941,16.311 36.934,10.87 44.138,10.87
NetC9_1 on Top Layer "VOUT1" (solid, pour order 6): 14.491,17.81 14.44,17.759 12.101,17.759 9.303,15.828 3.742,15.828 3.742,10.41 2.17,10.41 2.17,1.916 10.066,1.916 10.104,1.954 10.243,2.093 10.243,9.515 10.243,9.934 8.467,11.711 8.467,12.27 8.467,13.882 14.063,13.882 14.477,14.296
NetC1_1 on Top Layer "TOP  VIN2" (solid, pour order 4): 14.104,28.831 14.583,28.688 14.415,28.688 14.415,28.52 14.415,25.628 23.251,25.628 23.279,25.656 23.319,25.696 23.319,49.391 17.337,49.391 17.293,49.346
NetC7_2 on Top Layer "TOP - SW" (solid, pour order 2): 9.299,20.591 13.588,20.591 13.871,20.591 13.871,20.875 13.871,30.404 16.362,30.404 16.539,30.404 16.813,30.404 17.557,30.404 17.557,33.549 17.557,37.252 14.764,37.252 14.764,33.549 10.779,29.564 10.471,29.256 10.471,22.887 9.64,22.887 8.856,22.102
NetC1_1 on Top Layer "TOP - VIN" (solid, pour order 0): 8.298,49.844 8.287,49.833 8.287,24.637 8.86,24.637 9.266,24.637 9.667,24.637 10.089,24.637 10.438,24.637 10.438,26.383 10.397,29.514 11.154,30.499 13.96,33.304 14.384,33.729 14.384,37.513 17.299,37.513 17.263,40.969 17.293,40.999 17.293,49.814
NetC1_1 on POWER "POWER-No Net" (solid, pour order 16): 0.021,49.994 0.023,49.992 49.972,49.992 49.972,0.008 49.971,0.01 0.04,0.01
GND2 on GNDS "GND2" (solid, pour order 20): 23.602,0.005 23.606,0.01 49.971,0.01 49.971,49.994 49.97,49.994 49.877,49.901 23.658,49.901
GND on GNDS "GND1" (solid, pour order 18): 23.593,0.166 0.196,0.166 0.04,0.01 0.021,0.029 0.021,49.994 23.454,49.994 23.593,49.855
GND2 on Bottom Layer "bot - gnd2" (solid, pour order 36): 50.031,49.962 49.911,50.082 23.563,50.082 23.563,0.02 23.742,0.2 50.091,0.2
GND on Bottom Layer "bot - gnd1" (solid, pour order 34): 0.089,49.962 23.503,49.962 23.323,49.783 23.323,0.14 0.208,0.14 0.029,-0.04

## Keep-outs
Keep-Out Layer:
  text ".Layer_Name" at 14.656,-21.806 h1.52

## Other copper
Top Layer:
  text ".Layer_Name" at 14.656,-21.806 h1.52
Bottom Layer:
  text ".Layer_Name" at 14.656,-21.806 h1.52

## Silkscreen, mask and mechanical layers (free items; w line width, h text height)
Top Overlay:
  lines w0.254: 0.019,-0.011 0.019,49.996 0.021,49.994 49.97,49.994 49.972,49.992 49.972,0.008 49.971,0.01 0.04,0.01 ; 0.035,10.211 50.001,10.211 ; 0.055,40.233 49.927,40.233
  text "VOUT3" at 42.021,48.99 h0.64
  text "GND" at 39.285,48.96 h0.64
  text "GND" at 5.964,48.919 h0.64
  text "VIN" at 9.245,48.921 h0.64
  text "PMP20550_RevA" at 15.028,41.876 h1.52
  text "30x50 mm" at 44.623,11.025 h0.64
  text "50x50 mm" at 44.579,0.857 h0.64
  text "GND" at 31.416,0.649 h0.64
  text "GND" at 11.251,0.595 h0.64
  text "VOUT1" at 7.071,0.55 h0.64
  text "VOUT2" at 34.168,0.553 h0.64
  text ".Layer_Name" at 14.656,-21.806 h1.52
Bottom Overlay:
  text ".Layer_Name" at 14.656,-21.806 h1.52
Top Paste:
  text ".Layer_Name" at 14.656,-21.806 h1.52
Bottom Paste:
  text ".Layer_Name" at 14.656,-21.806 h1.52
Top Solder:
  text ".Layer_Name" at 14.656,-21.806 h1.52
  text ".Layer_Name" at 14.656,-21.806 h1.52
Bottom Solder:
  text ".Layer_Name" at 14.656,-21.806 h1.52
Drill Guide:
  text ".Layer_Name" at 14.656,-21.806 h1.52
M1 Board Outline:
  text ".Layer_Name" at 14.656,-21.806 h1.52
M2 Board Dimensions:
  rectangle: 0,-6.985 3.175,-3.81
  rectangle: 3.175,-10.16 12.7,-6.985
  lines w0.178: 0,-6.985 25.4,-6.985 ; 3.175,-10.16 3.175,-3.81 ; 6.35,-10.16 6.35,-3.81 ; 12.7,-10.16 12.7,-3.81 ; 19.05,-10.16 19.05,-3.81 ; 0,-10.16 25.4,-10.16 25.4,-3.81 0,-3.81 0,-10.16
  text ".Layer_Name" at 14.656,-21.806 h1.52
M3 3D STEP Top:
  text ".Layer_Name" at 14.656,-21.806 h1.52
M4 3D STEP Bottom:
  text ".Layer_Name" at 14.656,-21.806 h1.52
M5 Assembly Top:
  lines w0.254: -7.417,-23.626 160.223,-23.626 ; -7.417,-18.462 160.274,-18.462 ; -7.417,-13.297 -7.417,-28.791 94.31,-28.791 160.274,-28.791 160.274,-13.297 -7.404,-13.297 -7.404,-28.791 32.614,-28.791 ; 55.194,-28.791 55.194,-13.297 ; 87.376,-18.462 87.376,-13.297 ; 108.712,-18.462 108.712,-13.297 ; 124.511,-28.956 124.511,-23.804
  text "COMPONENTS MARKED 'DNP' SHOULD NOT BE POPULATED." at 29.299,-8.09 h1.52
  text "ASSEMBLY VARIANT:" at 29.286,-11.024 h1.52
  text ".VariantName" at 55.601,-11.024 h1.52
  text "PCB VIEWED FROM TOP SIDE" at -5.804,-16.654 h1.52
  text "BOARD #:" at 57.099,-16.654 h1.52
  text ".PRJ_Number" at 70.955,-16.654 h1.52
  text "REV:" at 92.405,-16.654 h1.52
  text ".PCB_Rev" at 99.809,-16.654 h1.52
  text "SVN REV:" at 113.69,-16.654 h1.52
  text ".VersionControl_RevNumber" at 126.543,-16.654 h1.52
  text "TID #:" at 57.099,-21.819 h1.52
  text ".TID" at 70.955,-21.819 h1.52
  text "PLOT NAME =" at -5.804,-27.034 h1.52
  text ".plot_File_Name" at 14.656,-27.034 h1.52
  text "GENERATED    :" at 57.15,-27.034 h1.52
  text ".Print_Date" at 79.235,-27.034 h1.52
  text ".Print_Time" at 97.752,-27.034 h1.52
  text "TEXAS INSTRUMENTS" at 129.87,-27.034 h1.52
M6 Assembly Bottom:
  lines w0.254: -7.429,-18.474 160.261,-18.474 ; -7.379,-23.639 160.261,-23.639 ; 28.334,-28.969 28.334,-23.817 ; 44.133,-18.474 44.133,-13.31 ; 65.468,-18.474 65.468,-13.31 ; 97.65,-28.804 97.65,-13.31 ; 120.231,-28.804 160.249,-28.804 160.249,-13.31 -7.429,-13.31 -7.429,-28.804 58.534,-28.804 160.261,-28.804 160.261,-13.31
  text "COMPONENTS MARKED 'DNP' SHOULD NOT BE POPULATED." at 154.991,-8.077 h1.52
  text ".VariantName" at 128.473,-11.024 h1.52
  text "ASSEMBLY VARIANT:" at 154.864,-11.024 h1.52
  text ".VersionControl_RevNumber" at 26.302,-16.667 h1.52
  text "SVN REV:" at 39.154,-16.667 h1.52
  text ".PCB_Rev" at 53.035,-16.667 h1.52
  text "REV:" at 60.439,-16.667 h1.52
  text ".PRJ_Number" at 81.89,-16.667 h1.52
  text "BOARD #:" at 95.745,-16.667 h1.52
  text "PCB VIEWED FROM BOTTOM SIDE" at 158.648,-16.667 h1.52
  text ".TID" at 81.89,-21.831 h1.52
  text "TID #:" at 95.745,-21.831 h1.52
  text "TEXAS INSTRUMENTS" at 22.974,-27.047 h1.52
  text ".Print_Time" at 55.093,-27.047 h1.52
  text ".Print_Date" at 73.609,-27.047 h1.52
  text "GENERATED    :" at 95.694,-27.047 h1.52
  text ".plot_File_Name" at 138.189,-27.047 h1.52
  text "PLOT NAME =" at 158.648,-27.047 h1.52
M9 Title Sheet:
  drawing of 57 lines, arcs and shapes, not listed
  text "1" at 18.792,204.127 h1.78
  text "2" at 82.182,204.127 h1.78
  text "3" at 145.411,204.127 h1.78
  text "4" at 209.08,204.127 h1.78
  text "5" at 272.555,204.127 h1.78
  text "6" at 336.182,204.127 h1.78
  text "A" at -10.579,175.095 h1.78
  text "A" at 365.341,175.095 h1.78
  text "B" at -10.579,114.643 h1.78
  text "B" at 365.341,114.643 h1.78
  text "C" at -10.579,54.318 h1.78
  text "C" at 365.341,54.318 h1.78
  text "PROJECT TITLE:" at 288.125,7.048 h1.14
  text ".PRJ_Title" at 289.395,3.662 h1.78
  text "DESIGNED FOR:" at 288.125,-0.597 h1.14
  text ".PRJ_Customer" at 289.395,-4.153 h1.78
  text "D" at -10.579,-5.88 h1.78
  text "D" at 365.341,-5.88 h1.78
  text "FILE NAME:" at 288.125,-8.217 h1.14
  text ".PCB_File_Name_No_Path" at 289.395,-11.265 h1.78
  text "Texas Instruments (TI) and/or its licensors do not warrant the accuracy or completeness of this specification" at 161.9,-15.376 h1.14
  text "ENGINEER:" at 288.125,-15.583 h1.14
  text "LAYOUT BY:" at 326.352,-15.583 h1.14
  text "or any information contained therein. TI and/or its licensors do not warrant that this design will meet" at 160.757,-18.237 h1.14
  text ".PRJ_Engineer" at 289.395,-19.52 h1.78
  text ".PCB_Layout" at 327.635,-19.52 h1.78
  text "the specifications, will be suitable for your application or fit for any particular purpose, or will operate in" at 160.757,-21.099 h1.14
  text ".Layer_Name" at 14.656,-21.806 h1.52
  text "ALTIUM DESIGNER VERSION:" at 326.352,-23.457 h1.14
  text "an implementation. TI and/or its licensors do not warrant that the design is production worthy. You should" at 160.757,-23.961 h1.14
  text "completely validate and test your design implementation to confirm the system functionality for your application." at 161.9,-26.822 h1.14
  text ".print_Scale" at 289.395,-26.843 h1.78
  text ".Application_BuildNumber" at 327.635,-26.843 h1.78
  text "1" at 18.792,-32.093 h1.78
  text "2" at 82.182,-32.093 h1.78
  text "3" at 145.411,-32.093 h1.78
  text "4" at 209.08,-32.093 h1.78
  text "5" at 272.555,-32.093 h1.78
  text "6" at 336.182,-32.093 h1.78
M10 Fab Notes:
  drawing of 173 lines, arcs and shapes, not listed
  text "DESIGN INFORMATION" at 314.402,157.505 h1.52
  text "MIN. TRACK WIDTH:" at 298.03,152.933 h1.52
  text "8" at 325.874,152.933 h1.52
  text "MIL" at 329.805,152.933 h1.52
  text "MIN. CLEARANCE:" at 298.03,149.581 h1.52
  text "0.2" at 324.35,149.581 h1.52
  text "mm" at 329.805,149.581 h1.52
  text "MIN. VIA PAD SIZE:" at 298.03,146.228 h1.52
  text "24" at 325.113,146.228 h1.52
  text "MIL" at 329.805,146.228 h1.52
  text "0.05mm (2MIL)" at 315.683,142.628 h1.52
  text "MINIMUM ANNULAR RING" at 289.667,142.52 h1.52
  text "EXTERNAL" at 333.666,142.52 h1.52
  text "PER" at 294.747,139.522 h1.52
  text "IPC-D-275 CLASS 2 LEVEL C" at 300.335,139.522 h1.52
  text "MIL, HOLES" at 338.136,136.67 h1.52
  text "+/-" at 328.168,136.652 h1.52
  text "+/-" at 349.86,136.652 h1.52
  text "REGISTRATION TOLERANCES:" at 289.667,136.525 h1.52
  text "METAL" at 320.142,136.525 h1.52
  text "5" at 334.777,136.525 h1.52
  text "3" at 355.935,136.525 h1.52
  text "MIL" at 358.888,136.525 h1.52
  text "+/-" at 349.86,133.655 h1.52
  text "HOLE SIZE TOLERANCE (UNLESS OTHERWISE SPECIFIED):" at 289.667,133.528 h1.52
  text "3" at 355.935,133.528 h1.52
  text "MIL" at 358.888,133.528 h1.52
  text "MATERIAL:" at 287.768,128.208 h1.52
  text "FR-4 High Tg" at 312.824,124.643 h1.52
  text "FR-408" at 298.462,124.425 h1.52
  text "OTHER" at 336.257,124.425 h1.52
  text "X" at 308.889,124.333 h1.52
  text "62 MIL (1.6mm) +/-10%" at 306.592,120.292 h1.52
  text "THICKNESS:" at 289.667,120.184 h1.52
  text "X" at 303.337,120.184 h1.52
  text "OTHER" at 339.229,120.184 h1.52
  text "TOLERANCE:" at 289.667,116.17 h1.52
  text "X" at 310.986,116.17 h1.52
  text "ANSI IPC-6012 TYPE 3 CLASS 2" at 315.734,116.17 h1.52
  text "OTHER +/-" at 315.734,112.208 h1.52
  text "BOW & TWIST:" at 289.667,108.22 h1.52
  text "X" at 310.986,108.22 h1.52
  text "ANSI IPC-6012 TYPE 3 CLASS 2" at 315.734,108.22 h1.52
  text "OTHER +/-" at 315.734,104.194 h1.52
  text "DRILLING:" at 287.768,100.676 h1.52
  text "REFERENCE:" at 289.667,97.705 h1.52
  text "X" at 306.132,97.705 h1.52
  text "AS SHOWN" at 310.882,97.705 h1.52
  text "X" at 329.018,97.705 h1.52
  text "NC_DRILL FILES" at 332.498,97.705 h1.52
  text "PTH COPPER THICKNESS:" at 289.667,93.691 h1.52
  text "X" at 318.375,93.691 h1.52
  text "20-30 um" at 321.855,93.691 h1.52
  text "OTHER" at 340.067,93.691 h1.52
  text "BOARD FINISH:" at 287.768,89.653 h1.52
  text "SILKSCREEN:" at 291.711,86.656 h1.52
  text "X" at 315.81,86.656 h1.52
  text "TOP" at 319.01,86.656 h1.52
  text "X" at 328.764,86.656 h1.52
  text "BOTTOM" at 331.99,86.656 h1.52
  text "SILKSCREEN COLOR:" at 291.711,82.414 h1.52
  text "X" at 315.783,82.414 h1.52
  text "WHITE" at 319.01,82.414 h1.52
  text "OTHER" at 331.99,82.414 h1.52
  text "X" at 319.111,78.37 h1.52
  text "GREEN" at 322.338,78.37 h1.52
  text "OTHER" at 338.035,78.37 h1.52
  text "SOLDER RESIST COLOR:" at 291.711,78.096 h1.52
  text "X" at 319.111,74.052 h1.52
  text "MATTE" at 322.338,74.052 h1.52
  text "SEMI-GLOSS" at 338.023,74.036 h1.52
  text "IMMERSION GOLD (ENIG)" at 314.718,69.264 h1.52
  text "ENEPIG" at 348.691,69.18 h1.52
  text "SURFACE FINISH:" at 287.768,69.155 h1.52
  text "X" at 309.969,69.155 h1.52
  text "IMM. TIN/SILVER OR EQUIV" at 296.139,65.167 h1.52
  text "OTHER" at 332.498,65.167 h1.52
  text "ARRAY/PANEL:" at 287.768,60.621 h1.52
  text "CUT AND TRIM PER M1 BOARD OUTLINE" at 314.718,60.512 h1.52
  text "N.C. ROUTE" at 314.718,56.658 h1.52
  text "X" at 331.964,56.658 h1.52
  text "V. SCORE" at 336.714,56.658 h1.52
  text "CERTIFICATION:" at 287.768,53.178 h1.52
  text "MATERIALS AND WORKMANSHIP FOR ALL PCBS" at 306.183,53.178 h1.52
  text "TO MEET OR EXCEED THE REQUIREMENTS OF:" at 306.183,50.689 h1.52
  text "X" at 296.696,47.222 h1.52
  text "ANSI IPC-A-600F CLASS ->" at 300.227,47.222 h1.52
  text "X" at 341.859,47.222 h1.52
  text "2" at 344.88,47.222 h1.52
  text "1" at 336.879,47.184 h1.52
  text "3" at 353.872,47.184 h1.52
  text "X" at 317.373,43.171 h1.52
  text "RoHS" at 320.852,43.171 h1.52
  text "OTHER" at 337.22,43.171 h1.52
  text "PER ORDER" at 347.305,43.171 h1.52
  text "ALL BOARDS MUST MEET OR EXCEED UL94-V0 REQUIREMENTS." at 288.468,38.964 h1.52
  text "PCB MUST BEAR THE UL94V-0 UL REGISTERED MATERIAL ID NUMBER" at 288.468,35.916 h1.52
  text "ADDITIONAL REQUIREMENTS:" at 287.768,31.512 h1.52
  text "MICROSECTION:" at 289.667,28.591 h1.52
  text "YES" at 312.673,28.591 h1.52
  text "REQUIRED" at 334.555,24.625 h1.52
  text "BARE BOARD ELEC. TEST:" at 289.667,24.553 h1.52
  text "NONE" at 322.833,24.553 h1.52
  text "X" at 331.329,24.553 h1.52
  text "PER ORDER" at 349.592,24.553 h1.52
  text ".Layer_Name" at 14.656,-21.806 h1.52
M11 Gerber Information:
  lines w0.254: -7.417,-23.626 160.223,-23.626 ; -7.417,-18.462 160.274,-18.462 ; -7.417,-13.297 -7.417,-28.791 94.31,-28.791 160.274,-28.791 160.274,-13.297 -7.404,-13.297 -7.404,-28.791 32.614,-28.791 ; 55.194,-28.791 55.194,-13.297 ; 87.376,-18.462 87.376,-13.297 ; 108.712,-18.462 108.712,-13.297 ; 124.511,-28.956 124.511,-23.804
  text "ALL ARTWORK VIEWED FROM TOP SIDE" at -5.804,-16.654 h1.52
  text "BOARD #:" at 57.099,-16.654 h1.52
  text ".PRJ_Number" at 70.955,-16.654 h1.52
  text "REV:" at 92.405,-16.654 h1.52
  text ".PCB_Rev" at 99.809,-16.654 h1.52
  text "SVN REV:" at 113.69,-16.654 h1.52
  text ".VersionControl_RevNumber" at 126.543,-16.654 h1.52
  text "LAYER NAME =" at -5.804,-21.806 h1.52
  text "TID #:" at 57.099,-21.819 h1.52
  text ".TID" at 70.955,-21.819 h1.52
  text "PLOT NAME =" at -5.804,-27.034 h1.52
  text ".plot_File_Name" at 14.656,-27.034 h1.52
  text "GENERATED    :" at 57.15,-27.034 h1.52
  text ".Print_Date" at 79.235,-27.034 h1.52
  text ".Print_Time" at 97.752,-27.034 h1.52
  text "TEXAS INSTRUMENTS" at 129.87,-27.034 h1.52
M12 Stackup:
  text ".Layer_Name" at 14.656,-21.806 h1.52
M13 Component Bodies Top:
  text ".Layer_Name" at 14.656,-21.806 h1.52
M14 Component Bodies Bottom:
  text ".Layer_Name" at 14.656,-21.806 h1.52
M15 Courtyards Top:
  text ".Layer_Name" at 14.656,-21.806 h1.52
M16 Courtyards Bottom:
  text ".Layer_Name" at 14.656,-21.806 h1.52
Drill Drawing:
  text ".Layer_Name" at 14.656,-21.806 h1.52
M17 Embedded Cavity:
  text ".Layer_Name" at 14.656,-21.806 h1.52
M18 Embedded Assembly:
  text ".Layer_Name" at 14.656,-21.806 h1.52
M19 Embedded Keepout:
  text ".Layer_Name" at 14.656,-21.806 h1.52

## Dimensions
0,-10.16 to 25.4,-10.16 on M2 Board Dimensions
